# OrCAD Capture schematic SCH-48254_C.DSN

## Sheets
1 4. BRKT-Sensors: size B; title: FRDM-STBA-A8964; rev: C; company: Freescale Semiconductor; note: SCH-48254 PDF: SPF-48254; note: 6501 William Cannon Drive West; note: Austin, TX 78735-8598
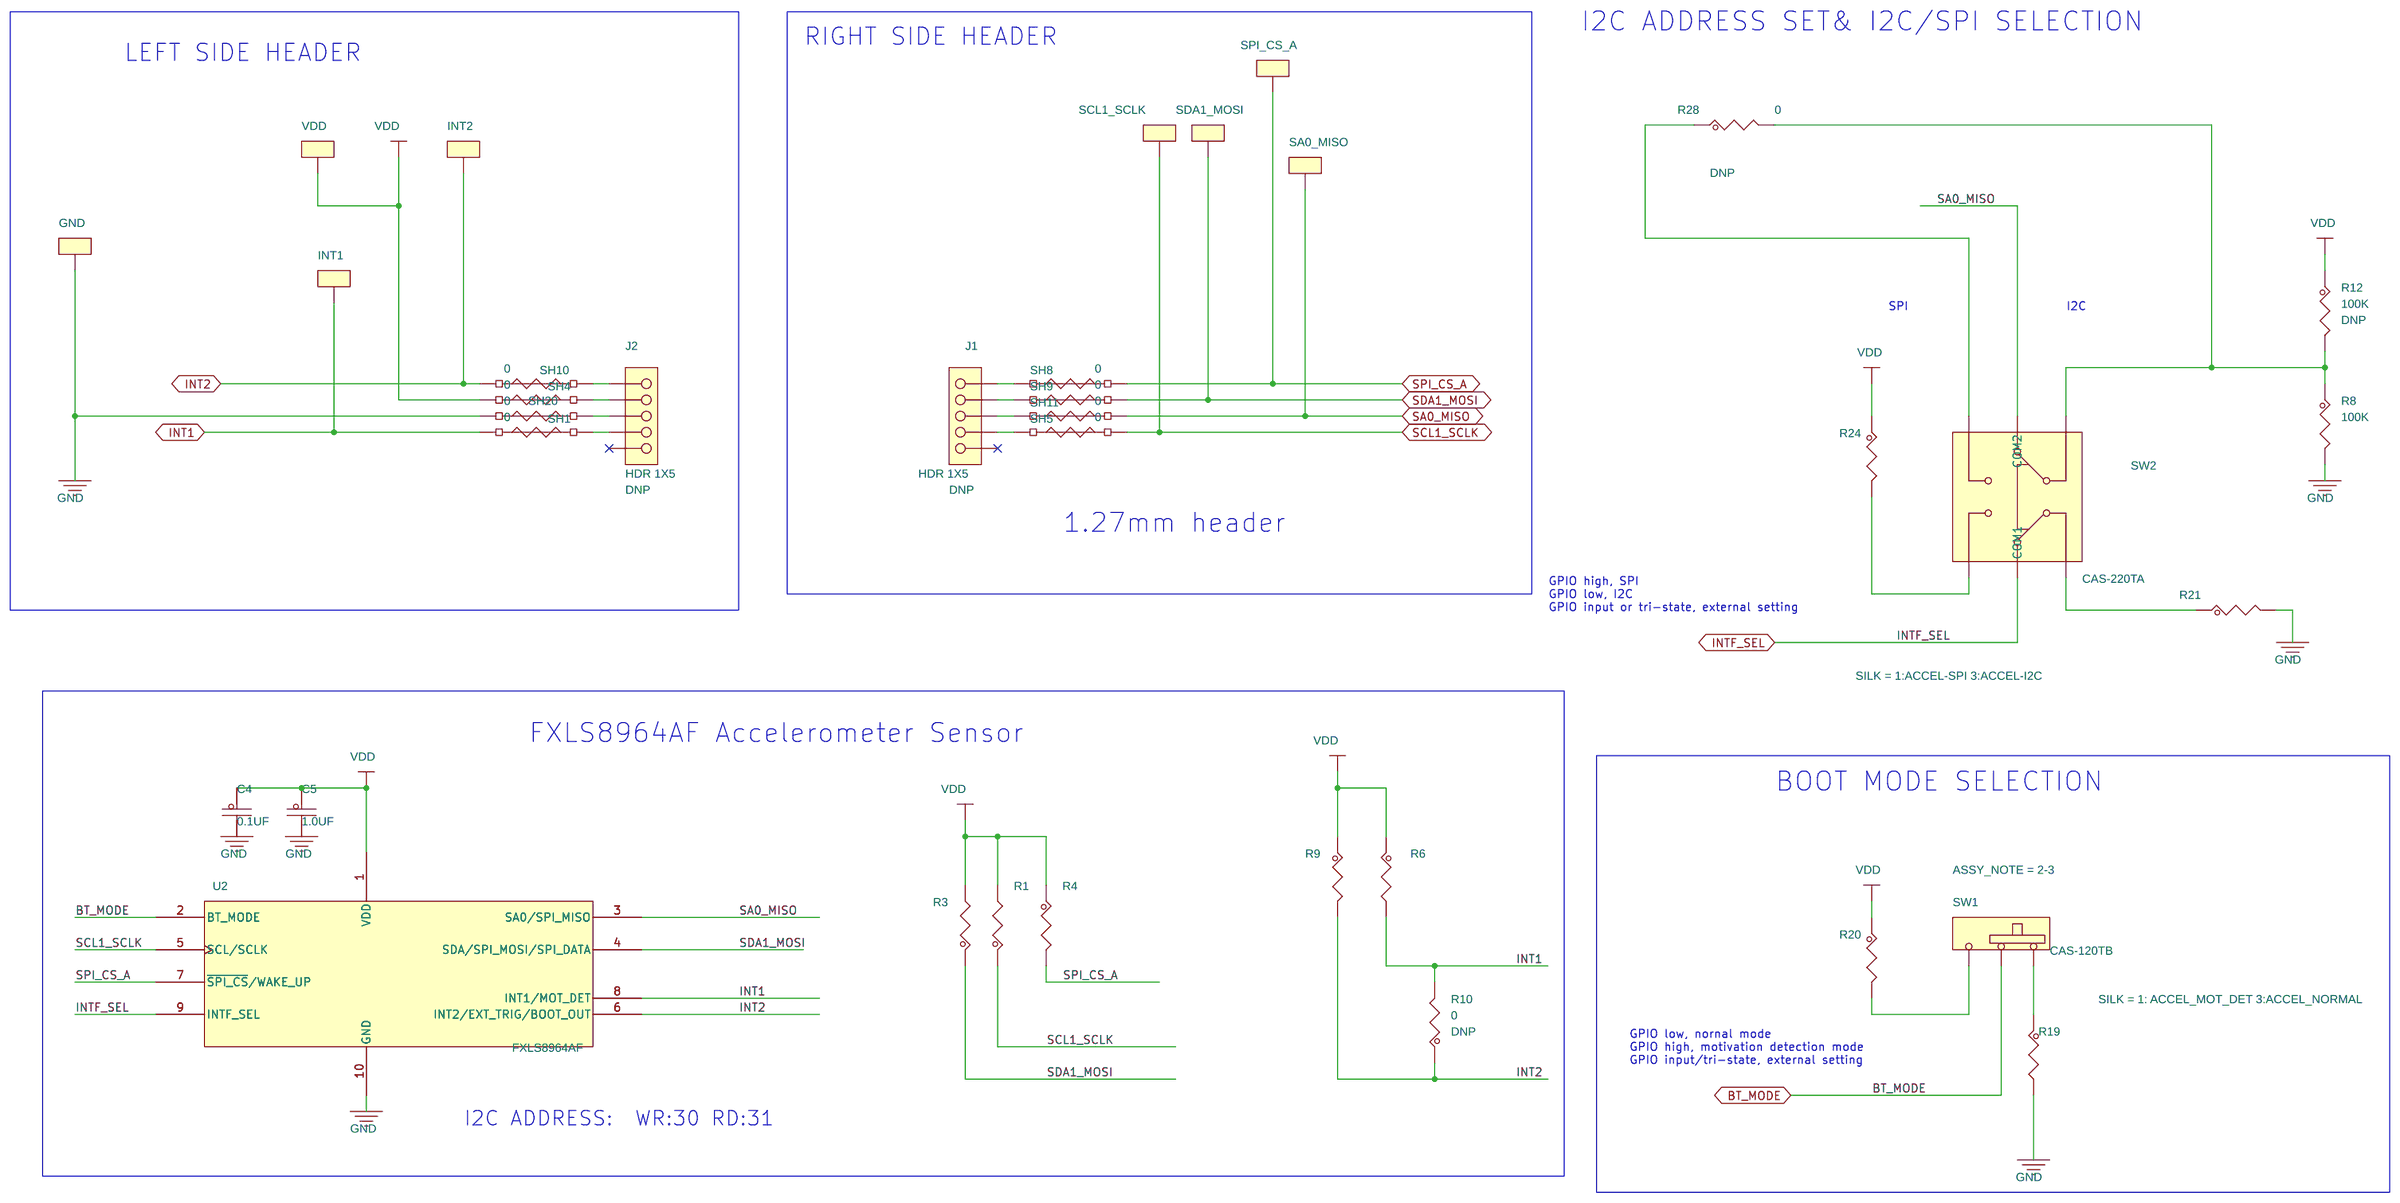
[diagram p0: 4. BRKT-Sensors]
2 1. Title Page: rev: X; company: NXP Semiconductors; note: SCH-XXXXX PDF: SPF-XXXXX
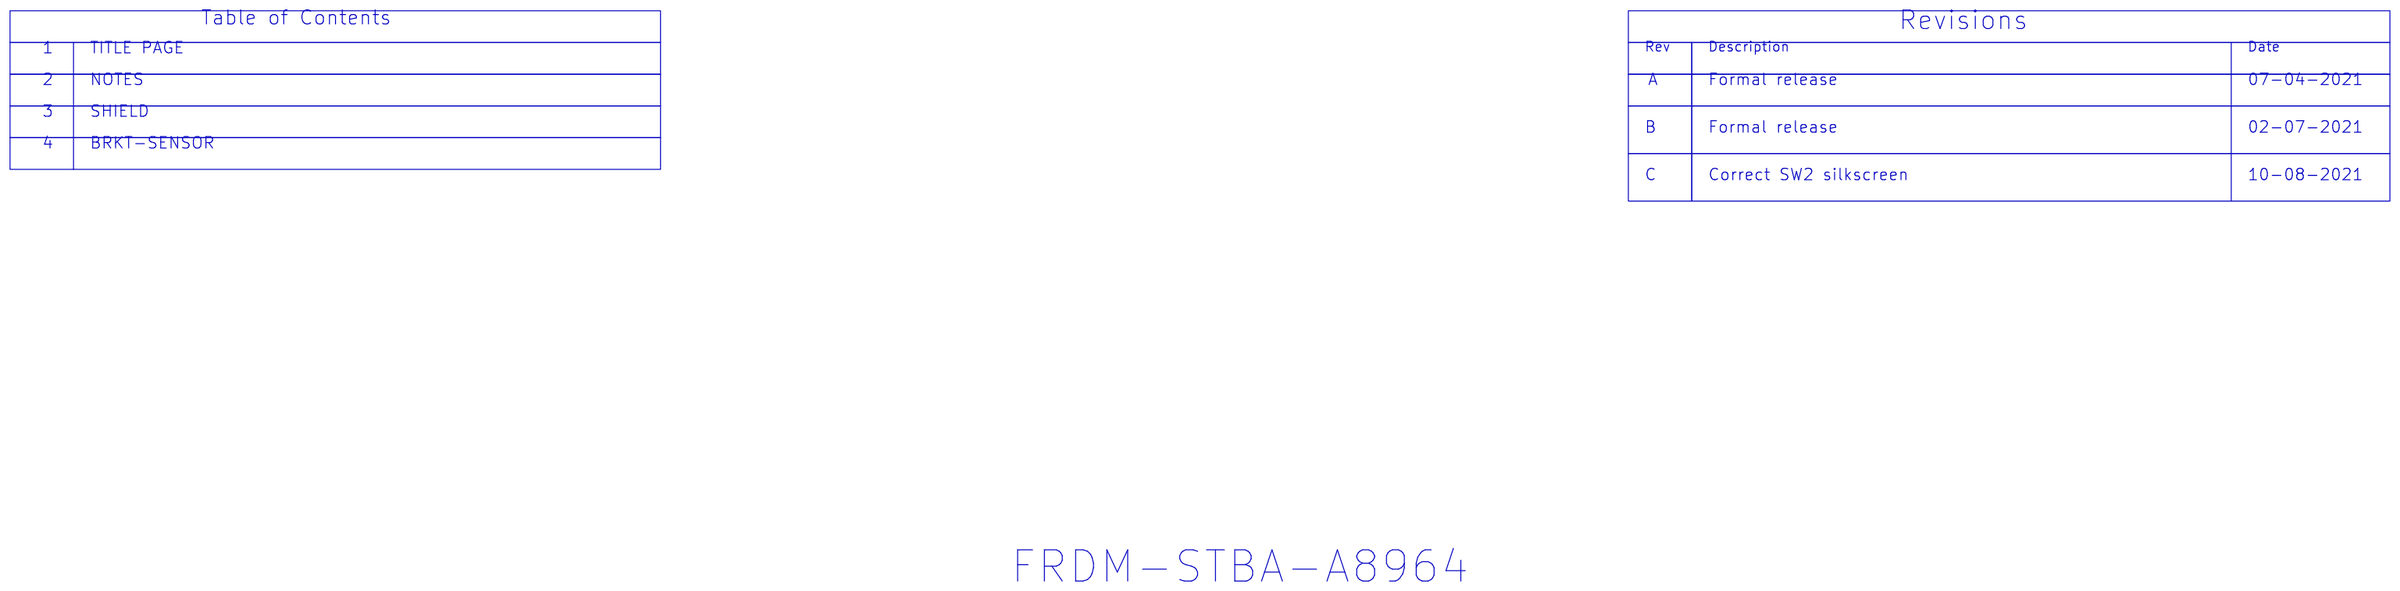
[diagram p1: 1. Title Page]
3 2. Notes
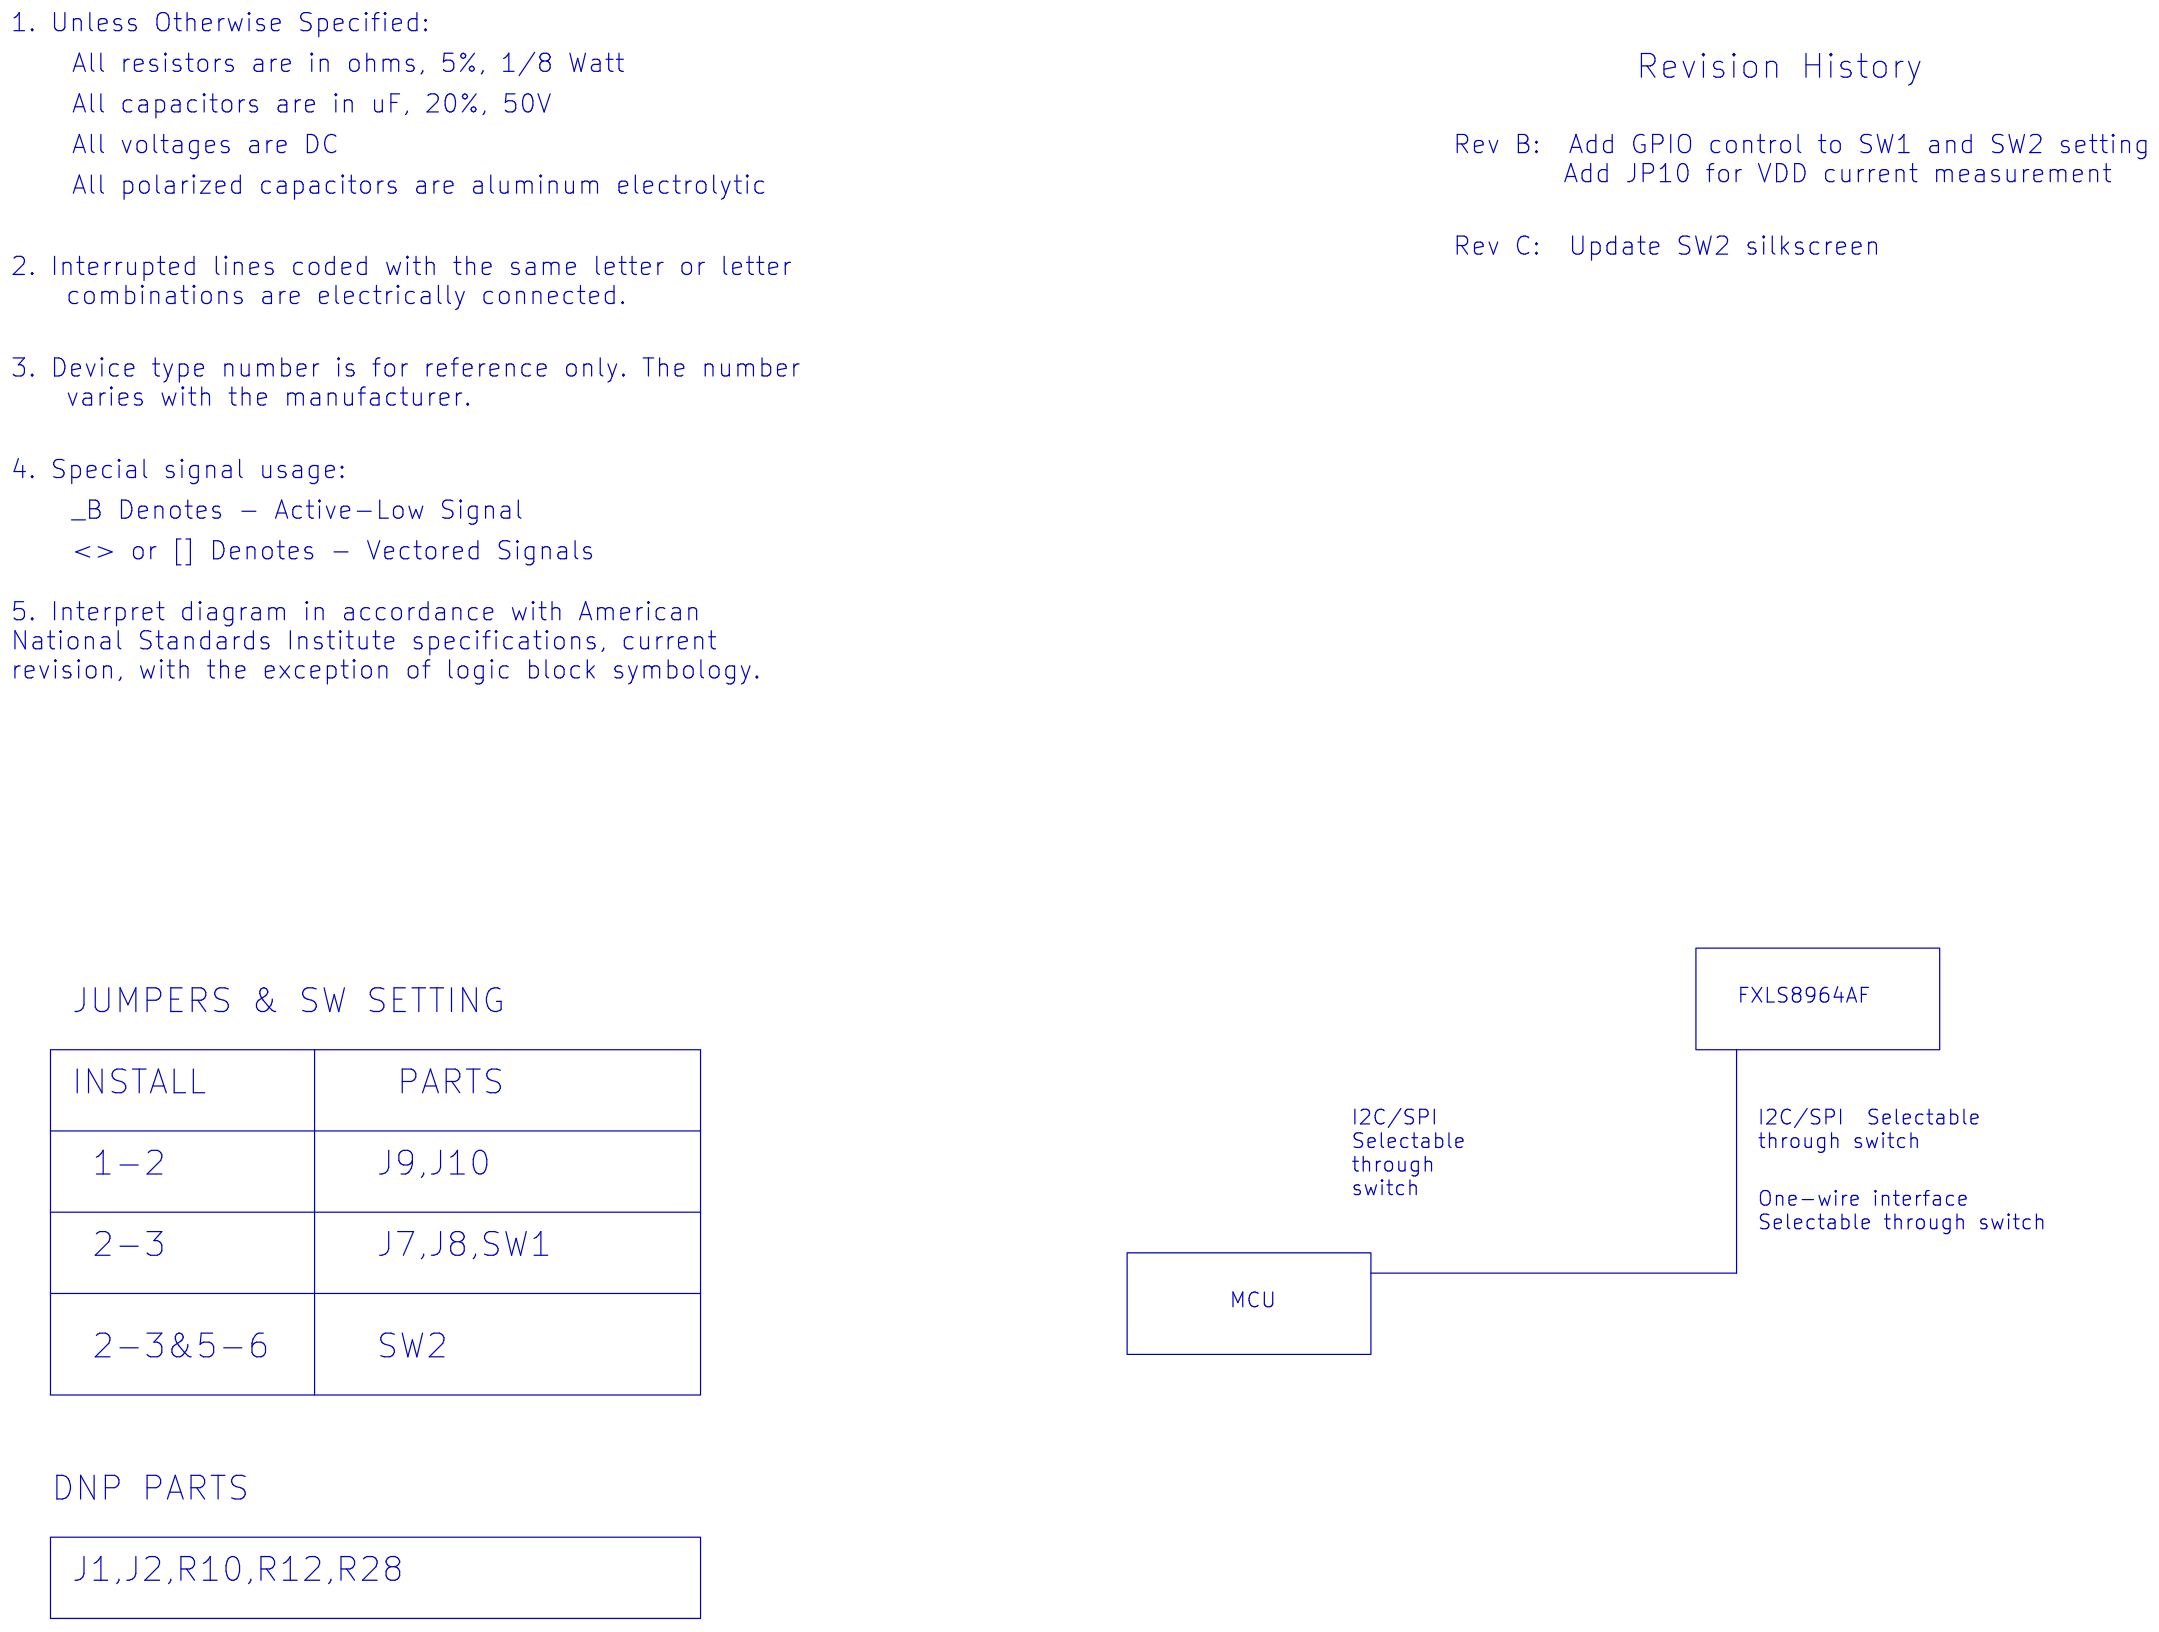
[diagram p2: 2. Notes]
4 3. Shield: size B
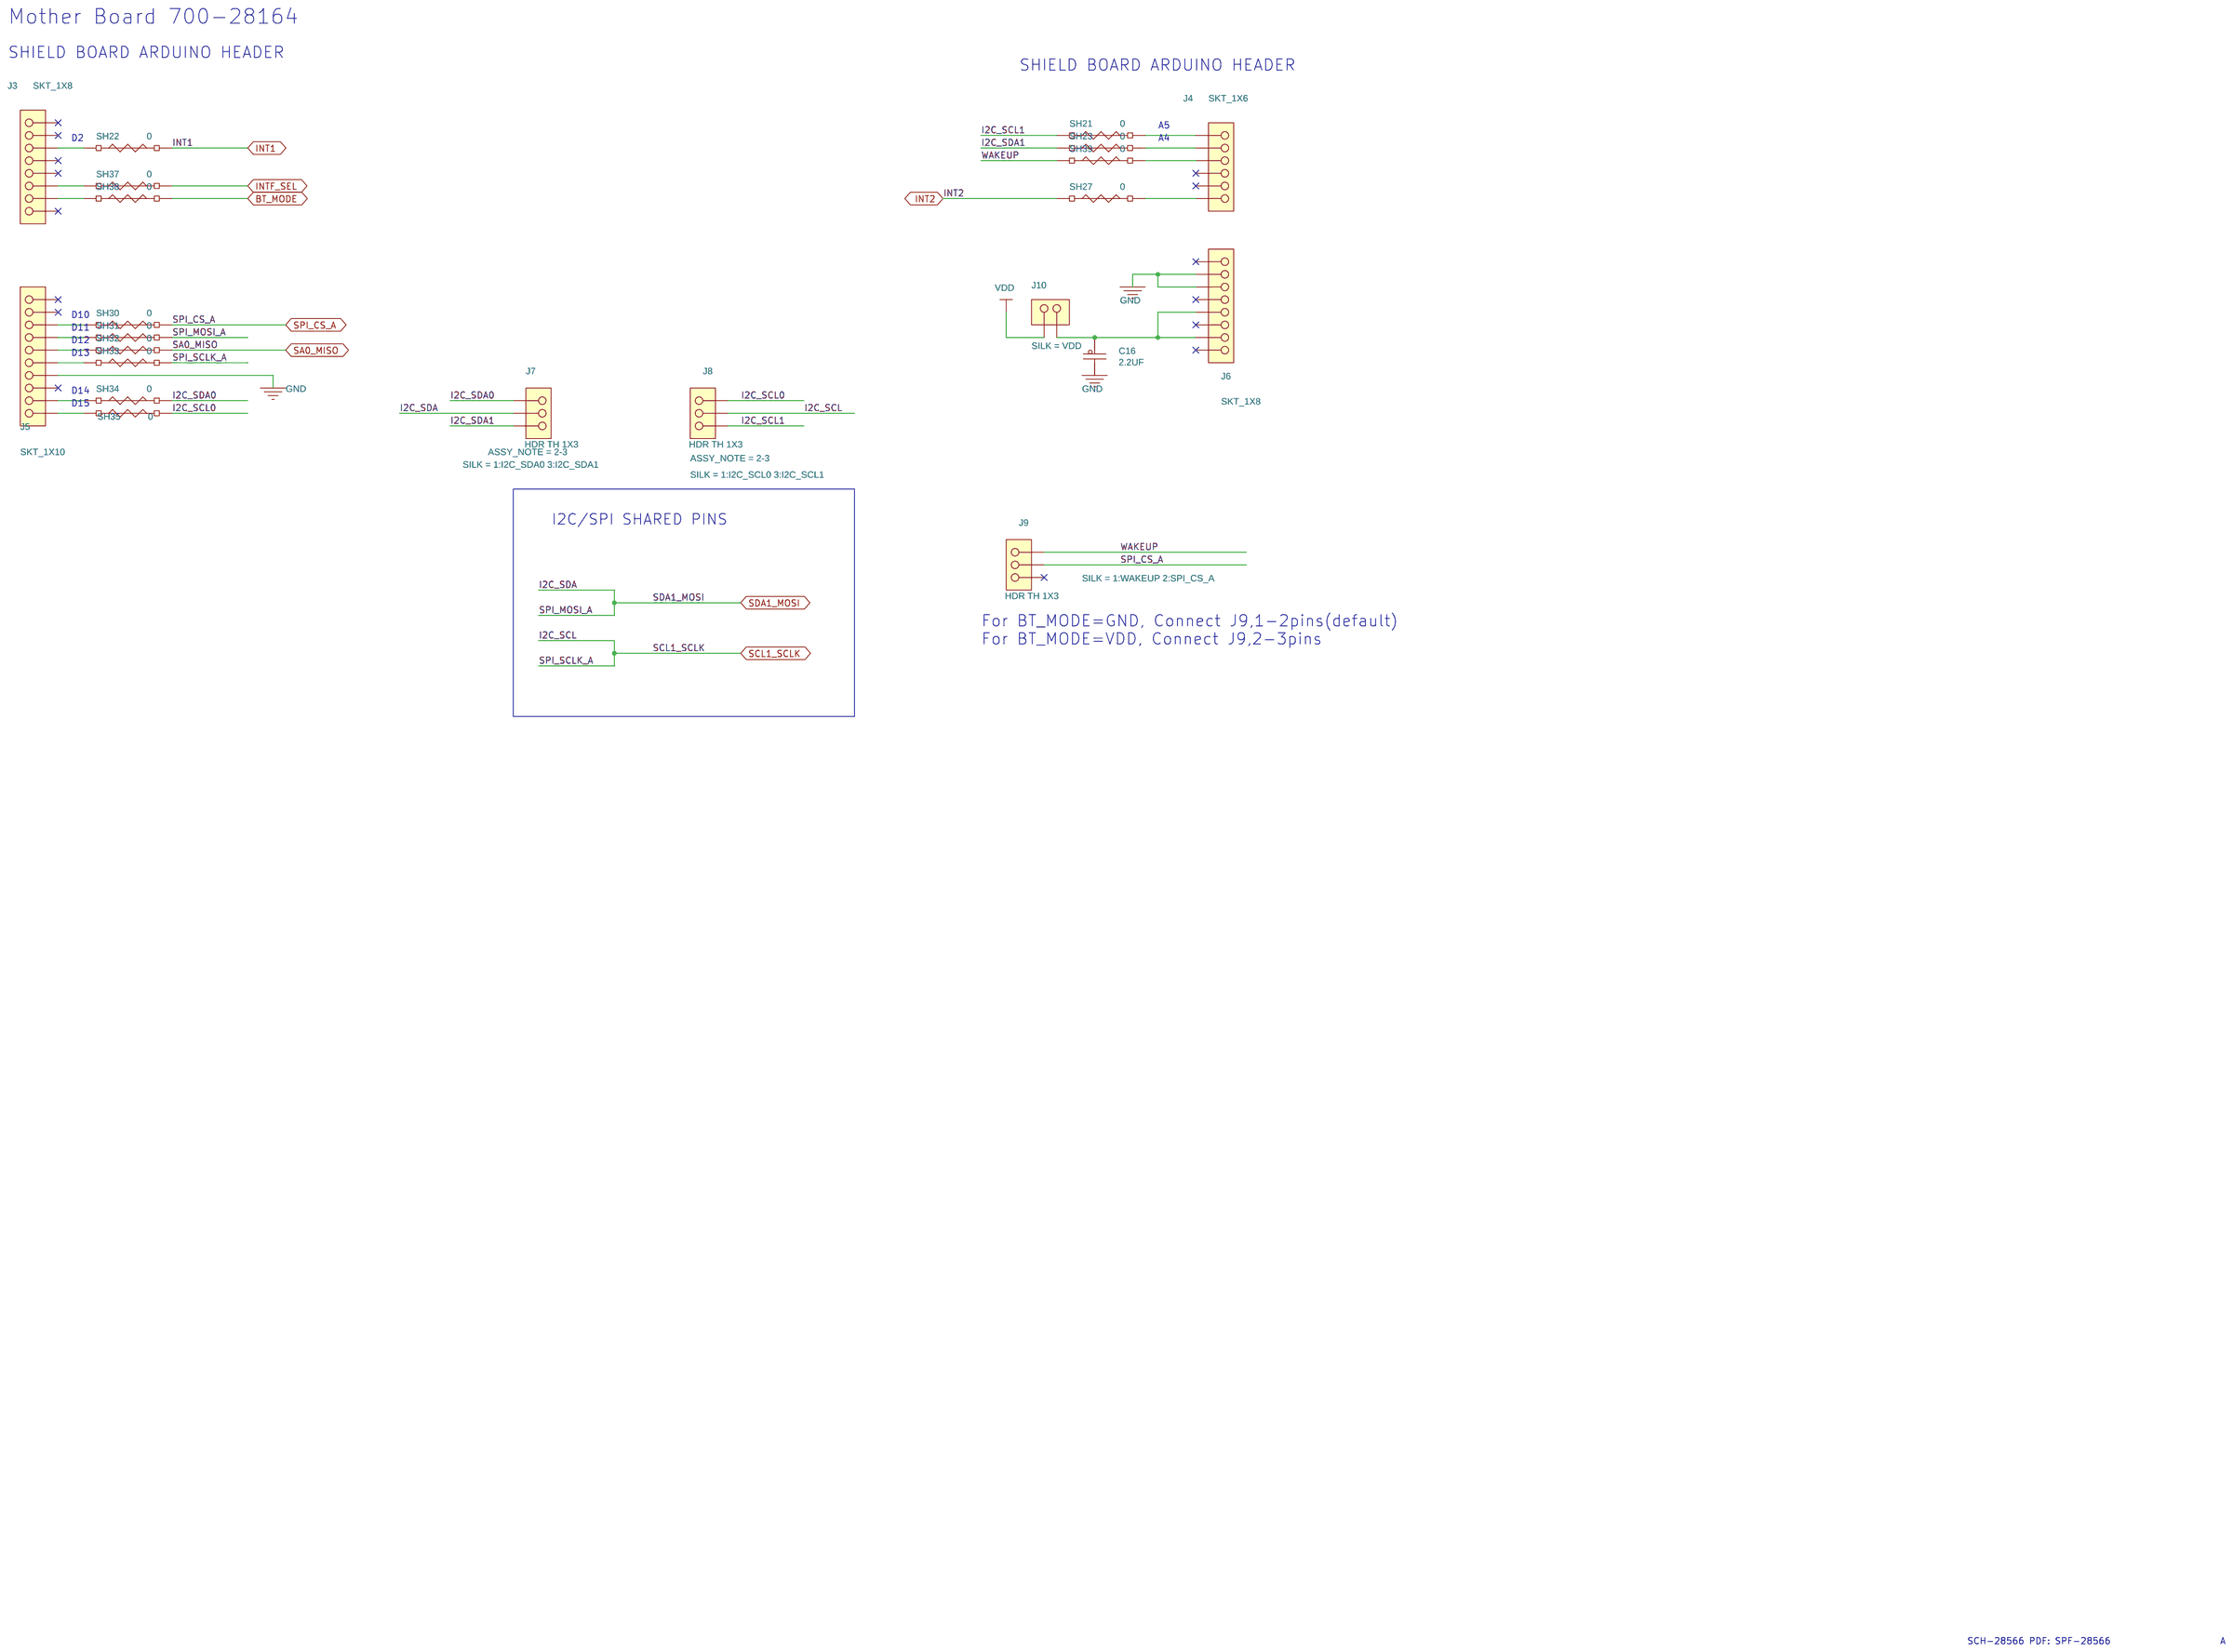
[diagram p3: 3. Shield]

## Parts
sheet 3. Shield
C16  2.2UF  [CC0402_25]
J3  SKT_1X8  [con_skt1x8_th]
J4  SKT_1X6  [con_skt1x6_th]
J5  SKT_1X10  [con_skt1x10_th]
J6  SKT_1X8  [con_skt1x8_th]
J7  HDR TH 1X3  [HDR103]
J8  HDR TH 1X3  [HDR103]
J9  HDR TH 1X3  [HDR103]
J10  HDR 1X2  [hdr1x2_1p27_th]
SH21  0  [SH0201]
SH22  0  [SH0201]
SH23  0  [SH0201]
SH27  0  [SH0201]
SH30  0  [SH0201]
SH31  0  [SH0201]
SH32  0  [SH0201]
SH33  0  [SH0201]
SH34  0  [SH0201]
SH35  0  [SH0201]
SH37  0  [SH0201]
SH38  0  [SH0201]
SH39  0  [SH0201]
sheet 4. BRKT-Sensors
C4  0.1UF  [CC0402_25]
C5  1.0UF  [CC0402_25]
GND  0805  [testpoint_122x049mil]
INT1  0805  [testpoint_122x049mil]
INT2  0805  [testpoint_122x049mil]
J1  HDR 1X5  [hdr1x5_50_th]
J2  HDR 1X5  [hdr1x5_50_th]
R1  4.7K  [RC0603]
R3  4.7K  [RC0603]
R4  10K  [RC0603]
R6  10K  [RC0603]
R8  100K  [RC0603_OV]
R9  10K  [RC0603]
R10  0  [RC0603]
R12  100K  [RC0603_OV]
R19  10K  [RC0603]
R20  10K  [RC0603]
R21  10K  [RC0603]
R24  10K  [RC0603]
R28  0  [RC0603_OV]
SA0_MISO  0805  [testpoint_122x049mil]
SCL1_SCLK  0805  [testpoint_122x049mil]
SDA1_MOSI  0805  [testpoint_122x049mil]
SH1  0  [SH0201]
SH4  0  [SH0201]
SH5  0  [SH0201]
SH8  0  [SH0201]
SH9  0  [SH0201]
SH10  0  [SH0201]
SH11  0  [SH0201]
SH20  0  [SH0201]
SPI_CS_A  0805  [testpoint_122x049mil]
SW1  CAS-120TB  [sw3_1p75_3x6]
SW2  CAS-220TA  [sw6_1p75_4x5]
U2  FXLS8964AF  [DFN_10_0P4_2X2]
VDD  0805  [testpoint_122x049mil]

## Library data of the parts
C16 = CAP_NP: CAP CER 2.2UF 6.3V 20% X5R 0402; AGILE_PN: 150-76792; CAD_APPROVED: Yes; FPLIST: CC0402_25,CC0402_HD,0402_CC; HEIGHT: 0.55MM; MFG_NAME01: KEMET; MFG_PN01: C0402C225M9PACTU; Package Size: 0402; ROHS: Yes; Tolerance: 20%; VOLTAGE: 6.3V
J3 J6 = CONN_HDR_8X1: CON 1X8 SKT TH 100MIL SP 340H AU 394L; 3D_Mechanical_Footprint_File: ftp://fcl.am.freescale.net/ALLEGRO/step/con_skt1x8_th_394l.STEP; AGILE_PN: 210-80359; CAD_APPROVED: Yes; HEIGHT: 8.64MM; MFG_NAME01: SAMTEC; MFG_PN01: SSQ-108-03-F-S; ROHS: Yes; Temp Range: -55°C to +125°C
J4 = CONN_HDR_6X1: CON 1X6 SKT TH 100MIL SP 340H AU 394L; 3D_Mechanical_Footprint_File: ftp://fcl.am.freescale.net/ALLEGRO/step/con_skt1x6_th_394l.STEP; AGILE_PN: 210-80357; CAD_APPROVED: Yes; HEIGHT: 8.64MM; MFG_NAME01: SAMTEC; MFG_PN01: SSQ-106-03-F-S; ROHS: Yes; Temp Range: -55°C to +125°C
J5 = CONN_HDR_10X1: CON 1X10 SKT TH 100MIL SP 340H AU 394L; 3D_Mechanical_Footprint_File: ftp://fcl.am.freescale.net/ALLEGRO/step/con_skt1x10_th_394l.STEP; AGILE_PN: 210-80360; CAD_APPROVED: Yes; HEIGHT: 8.64MM; MFG_NAME01: SAMTEC; MFG_PN01: SSQ-110-03-F-S; ROHS: Yes; Temp Range: -55°C to +125°C
J7 = CONN_HDR_3X1: HDR 1x3 TH 100MIL SP 343H AU 100L; 3D_Mechanical_Footprint_File: ftp://fcl.am.freescale.net/ALLEGRO/step/hdr103.STEP; AGILE_PN: 210-80734; ASSY_NOTE: 2-3; CAD_APPROVED: Yes; HEIGHT: 8.72MM; MFG_NAME01: SAMTEC; MFG_PN01: TSW-103-07-F-S; ROHS: Yes; SILK: 1:I2C_SDA0 3:I2C_SDA1; Temp Range: -55°C to +125°C
J8 = CONN_HDR_3X1: HDR 1x3 TH 100MIL SP 343H AU 100L; 3D_Mechanical_Footprint_File: ftp://fcl.am.freescale.net/ALLEGRO/step/hdr103.STEP; AGILE_PN: 210-80734; ASSY_NOTE: 2-3; CAD_APPROVED: Yes; HEIGHT: 8.72MM; MFG_NAME01: SAMTEC; MFG_PN01: TSW-103-07-F-S; ROHS: Yes; SILK: 1:I2C_SCL0 3:I2C_SCL1; Temp Range: -55°C to +125°C
J9 = CONN_HDR_3X1: HDR 1x3 TH 100MIL SP 343H AU 100L; 3D_Mechanical_Footprint_File: ftp://fcl.am.freescale.net/ALLEGRO/step/hdr103.STEP; AGILE_PN: 210-80734; CAD_APPROVED: Yes; HEIGHT: 8.72MM; MFG_NAME01: SAMTEC; MFG_PN01: TSW-103-07-F-S; ROHS: Yes; SILK: 1:WAKEUP 2:SPI_CS_A; Temp Range: -55°C to +125°C
J10 = CONN_HDR_2X1: HDR 1X2 TH 1.27MM SP 205H AU 120L; 3D_Mechanical_Footprint_File: ftp://fcl.am.freescale.net/ALLEGRO/step/hdr1x2_1p27_th.STEP; AGILE_PN: 210-82802; CAD_APPROVED: Yes; HEIGHT: 5.2MM; MFG_NAME01: Samtec; MFG_PN01: TMS-102-02-G-S; Package Type: Through Hole; ROHS: Yes; SILK: VDD; Temp Range: -55°C to +125°C
SH1 SH4 SH5 SH8-SH11 SH20-SH23 SH27 SH30-SH35 SH37-SH39 = RES_SHORT-2: ZERO OHM CUT TRACE 0201 PADS; NO PART TO ORDER; AGILE_PN: 470-76473; CAD_APPROVED: Yes; FPLIST: SH0201,SH0201_CC; HEIGHT: 0.1 MM; ROHS: Yes
C4 = CAP_NP: CAP CER 0.1UF 10V 10% X5R 0402; AGILE_PN: 150-75634; CAD_APPROVED: Yes; FPLIST: CC0402_25,CC0402_HD,0402_CC; HEIGHT: 0.64MM; MFG_NAME01: YAGEO AMERICA; MFG_PN01: CC0402KRX5R6BB104; Package Size: 0402; ROHS: Yes; Tolerance: 10%; VOLTAGE: 10V
C5 = CAP_NP: CAP CER 1.0UF 10V 10% X5R 0402; AGILE_PN: 150-75772; CAD_APPROVED: Yes; FPLIST: CC0402_25,CC0402_HD,0402_CC; HEIGHT: 0.6MM; MFG_NAME01: YAGEO AMERICA; MFG_PN01: CC0402KRX5R6BB105; Package Size: 0402; ROHS: Yes; VOLTAGE: 10V
GND SA0_MISO SCL1_SCLK SDA1_MOSI SPI_CS_A VDD = TEST_POINT: TEST POINT PAD 3.1MMX1.25MM SMT AEC-Q200 0805; AGILE_PN: 211-79608; CAD_APPROVED: Yes; HEIGHT: 1.45MM; MFG_NAME01: KOA SPEER; MFG_PN01: RCTCTE; Package Size: 2X1.25x1.45MM; Package Type: SMT; ROHS: Yes
INT1 INT2 = TEST_POINT: TEST POINT PAD 3.1MMX1.25MM SMT AEC-Q200 0805; 3D_Mechanical_Footprint_File: ftp://fcl.am.freescale.net/ALLEGRO/step/testpoint_122x049mil.STEP; AGILE_PN: 211-79608; CAD_APPROVED: Yes; HEIGHT: 1.45MM; MFG_NAME01: KOA SPEER; MFG_PN01: RCTCTE; Package Size: 2X1.25x1.45MM; Package Type: SMT; ROHS: Yes
J1 J2 = CONN_HDR_5X1: HDR 1X5 TH 50MIL SP 159H AU 90L; 3D_Mechanical_Footprint_File: ftp://fcl.am.freescale.net/ALLEGRO/step/hdr1x5_50_th.STEP; AGILE_PN: 210-82660; ASSY_OPT: DNP; CAD_APPROVED: Yes; HEIGHT: 4.04MM; MFG_NAME01: SAMTEC; MFG_PN01: FTS-105-01-L-S; Package Type: Through Hole; ROHS: Yes; Temp Range: -55°C to +125°C
R1 R3 = RES: RES MF 4.7K 1/10W 5% 0603; AGILE_PN: 470-75414; CAD_APPROVED: Yes; FPLIST: RC0603_OV,RC0603,0603_CC; HEIGHT: 0.55 MM; MFG_NAME01: VISHAY INTERTECHNOLOGY; MFG_PN01: CRCW06034K70JNEA; ROHS: Yes; Tolerance: 5%
R4 R6 R9 R19-R21 R24 = RES: RES MF 10K 1/10W 5% 0603; AGILE_PN: 470-75410; CAD_APPROVED: Yes; FPLIST: RC0603_OV,RC0603,0603_CC; HEIGHT: 0.55MM; MFG_NAME01: BOURNS; MFG_PN01: CR0603-JW-103ELF; ROHS: Yes; Temp Range: –55 °C to +155 °C; Tolerance: 5%
R8 = RES: RES MF 100K 1/10W 5% 0603; AGILE_PN: 470-75444; CAD_APPROVED: Yes; FPLIST: RC0603_OV,RC0603,0603_CC; HEIGHT: 0.6MM; MFG_NAME01: BOURNS; MFG_PN01: CR0603-JW-104ELF; ROHS: Yes; Tolerance: 5%
R10 = RES: RES MF ZERO OHM 1/10W 1% 0603; AGILE_PN: 470-80217; ASSY_OPT: DNP; CAD_APPROVED: Yes; FPLIST: RC0603_OV,RC0603,R603-X2,0603_CC; HEIGHT: 0.55 MM; MFG_NAME01: MULTICOMP; MFG_PN01: MC0603SAF0000T5E; ROHS: Yes; Tolerance: 1%
R12 = RES: RES MF 100K 1/10W 5% 0603; AGILE_PN: 470-75444; ASSY_OPT: DNP; CAD_APPROVED: Yes; FPLIST: RC0603_OV,RC0603,0603_CC; HEIGHT: 0.6MM; MFG_NAME01: BOURNS; MFG_PN01: CR0603-JW-104ELF; ROHS: Yes; Tolerance: 5%
R28 = RES: RES MF ZERO OHM 1/10W -- 0603; AGILE_PN: 470-80866; ASSY_OPT: DNP; CAD_APPROVED: Yes; FPLIST: RC0603_OV,RC0603,R603-X2,0603_CC,IND_0603HP_NSP,CC0603_OV_NSP; HEIGHT: 0.6MM; MFG_NAME01: YAGEO AMERICA; MFG_PN01: RC0603FR-070RL; ROHS: Yes; Temp Range: –55 °C to +155 °C
SW1 = SW3_SPDT_SLD: SW SPDT SLD 100MA 6V SMD; 3D_Mechanical_Footprint_File: ftp://fcl.am.freescale.net/ALLEGRO/step/sw3_1p75_3x6.STEP; AGILE_PN: 510-78101; ASSY_NOTE: 2-3; CAD_APPROVED: Yes; HEIGHT: 2.5MM; MFG_NAME01: NIDEC COPAL ELECTRONICS CORP; ROHS: Yes; SILK: 1: ACCEL_MOT_DET 3:ACCEL_NORMAL
SW2 = SW_SL_DPDT_6P: SW DPDT SLIDE 24VDC 25mA SMD; 3D_Mechanical_Footprint_File: ftp://fcl.am.freescale.net/ALLEGRO/step/sw6_1p75_4x5.step; AGILE_PN: 510-78098; CAD_APPROVED: Yes; HEIGHT: 2.5MM; MFG_NAME01: NIDEC COPAL ELECTRONICS CORP; ROHS: Yes; SILK: 1:ACCEL-SPI 3:ACCEL-I2C; Temp Range: -40 to +85&#8451;; Temp_Range: -40 to +85&#8451;
U2 = FXLS8962AF_DFN10: IC ACCELEROMETER 3-AXIS 12BIT 1.71-3.6V AEC-Q100 DFN10; AGILE_PN: 312-83121; CAD_APPROVED: Yes; HEIGHT: 1 MM; MFG_NAME01: NXP SEMICONDUCTORS; MFG_PN01: FXLS8964AFR1; ROHS: Yes; Temp Range: -40  °C to +105 °C

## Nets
GND: C4.2 C5.2 C16.2 GND.1 J5.7 J6.6 J6.7 R8.2 R19.2 R21.2 SH20.2 U2.10(GND)
VDD: C4.1 C5.1 J10.1 R1.2 R3.2 R4.1 R6.1 R9.1 R12.1 R20.1 R24.1 SH4.2 U2.1(VDD) VDD.1
BT_MODE: SH38.2 SW1.2 U2.2(BT_MODE)
I2C_SCL0: J8.1 SH35.2
I2C_SCL1: J8.3 SH21.1
I2C_SDA0: J7.1 SH34.2
I2C_SDA1: J7.3 SH23.1
INT1: INT1.1 R6.2 R10.2 SH1.2 SH22.2 U2.8(INT1/MOT_DET)
INT2: INT2.1 R9.2 R10.1 SH10.2 SH27.1 U2.6(INT2/EXT_TRIG/BOOT_OUT)
INTF_SEL: SH37.2 SW2.2(COM1) U2.9(INTF_SEL)
SA0_MISO: SA0_MISO.1 SH11.2 SH32.2 SW2.5(COM2) U2.3(SA0/SPI_MISO)
SCL1_SCLK: J8.2 R1.1 SCL1_SCLK.1 SH5.2 SH33.2 U2.5(SCL/SCLK)
SDA1_MOSI: J7.2 R3.1 SDA1_MOSI.1 SH9.2 SH31.2 U2.4(SDA/SPI_MOSI/SPI_DATA)
SPI_CS_A: J9.2 R4.2 SH8.2 SH30.2 SPI_CS_A.1 U2.7(~{SPI_CS}/WAKE_UP)
WAKEUP: J9.1 SH39.1
N00622: J5.9 SH34.1
N00628: J5.10 SH35.1
N00993: C16.1 J6.2 J6.4 J10.2
N05692: J4.6 SH21.2
N05729: J4.5 SH23.2
N16652859: J5.4 SH31.1
N16652885: J5.5 SH32.1
N16652889: J5.6 SH33.1
N16653001: J5.3 SH30.1
N16659634: J4.1 SH27.2
N16701284: J3.3 SH22.1
N16711839: J2.1 SH10.1
N16711841: J2.2 SH4.1
N16711843: J2.3 SH20.1
N16711845: J2.4 SH1.1
N16711871: J1.1 SH8.1
N16711873: J1.2 SH9.1
N16711875: J1.3 SH11.1
N16711877: J1.4 SH5.1
N16715705: R20.2 SW1.1
N16718521: R21.1 SW2.3
N16718681: R24.2 SW2.1
N16719014: R8.1 R12.2 R28.2 SW2.6
N16719865: R28.1 SW2.4
N16720544: J3.6 SH37.1
N16720548: J3.7 SH38.1
N16721741: J4.4 SH39.2
N16884640: R19.1 SW1.3

Not connected (* = marked no-connect by the designer): J1 5*; J2 5*; J3 1* 2* 4* 5* 8*; J4 2* 3*; J5 1* 2* 8*; J6 1* 3* 5* 8*; J9 3*

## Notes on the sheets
sheet 1
- I2C ADDRESS SET& I2C/SPI SELECTION
- RIGHT SIDE HEADER
- LEFT SIDE HEADER
- SPI
- I2C
- 1.27mm header
- GPIO high, SPI
  GPIO low, I2C
  GPIO input or tri-state, external setting
- FXLS8964AF Accelerometer Sensor
- BOOT MODE SELECTION
- GPIO low, nornal mode
  GPIO high, motivation detection mode
  GPIO input/tri-state, external setting
- I2C ADDRESS:  WR:30 RD:31
sheet 2
- Table of Contents
- Revisions
- 1
- TITLE PAGE
- Rev
- Description
- Date
- 2
- NOTES
- A
- Formal release
- 07-04-2021
- 3
- SHIELD
- B
- Formal release
- 02-07-2021
- 4
- BRKT-SENSOR
- C
- Correct SW2 silkscreen
- 10-08-2021
- FRDM-STBA-A8964
sheet 3
- 1. Unless Otherwise Specified:
- All resistors are in ohms, 5%, 1/8 Watt
- Revision History
- All capacitors are in uF, 20%, 50V
- All voltages are DC
- Rev B:  Add GPIO control to SW1 and SW2 setting
          Add JP10 for VDD current measurement
- All polarized capacitors are aluminum electrolytic
- Rev C:  Update SW2 silkscreen
- 2. Interrupted lines coded with the same letter or letter
      combinations are electrically connected.
- 3. Device type number is for reference only. The number
      varies with the manufacturer.
- 4. Special signal usage:
- _B Denotes - Active-Low Signal
- <> or [] Denotes - Vectored Signals
- 5. Interpret diagram in accordance with American
  National Standards Institute specifications, current
  revision, with the exception of logic block symbology.
- JUMPERS & SW SETTING
- FXLS8964AF
- INSTALL
- PARTS
- I2C/SPI
  Selectable
  through
  switch
- I2C/SPI  Selectable
  through switch
- 1-2
- J9,J10
- One-wire interface
  Selectable through switch
- 2-3
- J7,J8,SW1
- MCU
- 2-3&5-6
- SW2
- DNP PARTS
- J1,J2,R10,R12,R28
sheet 4
- Mother Board 700-28164
- SHIELD BOARD ARDUINO HEADER
- SHIELD BOARD ARDUINO HEADER
- A5
- D2
- A4
- D10
- D11
- D12
- D13
- D14
- D15
- I2C/SPI SHARED PINS
- For BT_MODE=GND, Connect J9,1-2pins(default)
  For BT_MODE=VDD, Connect J9,2-3pins
- SCH-28566 PDF: SPF-28566
- A
